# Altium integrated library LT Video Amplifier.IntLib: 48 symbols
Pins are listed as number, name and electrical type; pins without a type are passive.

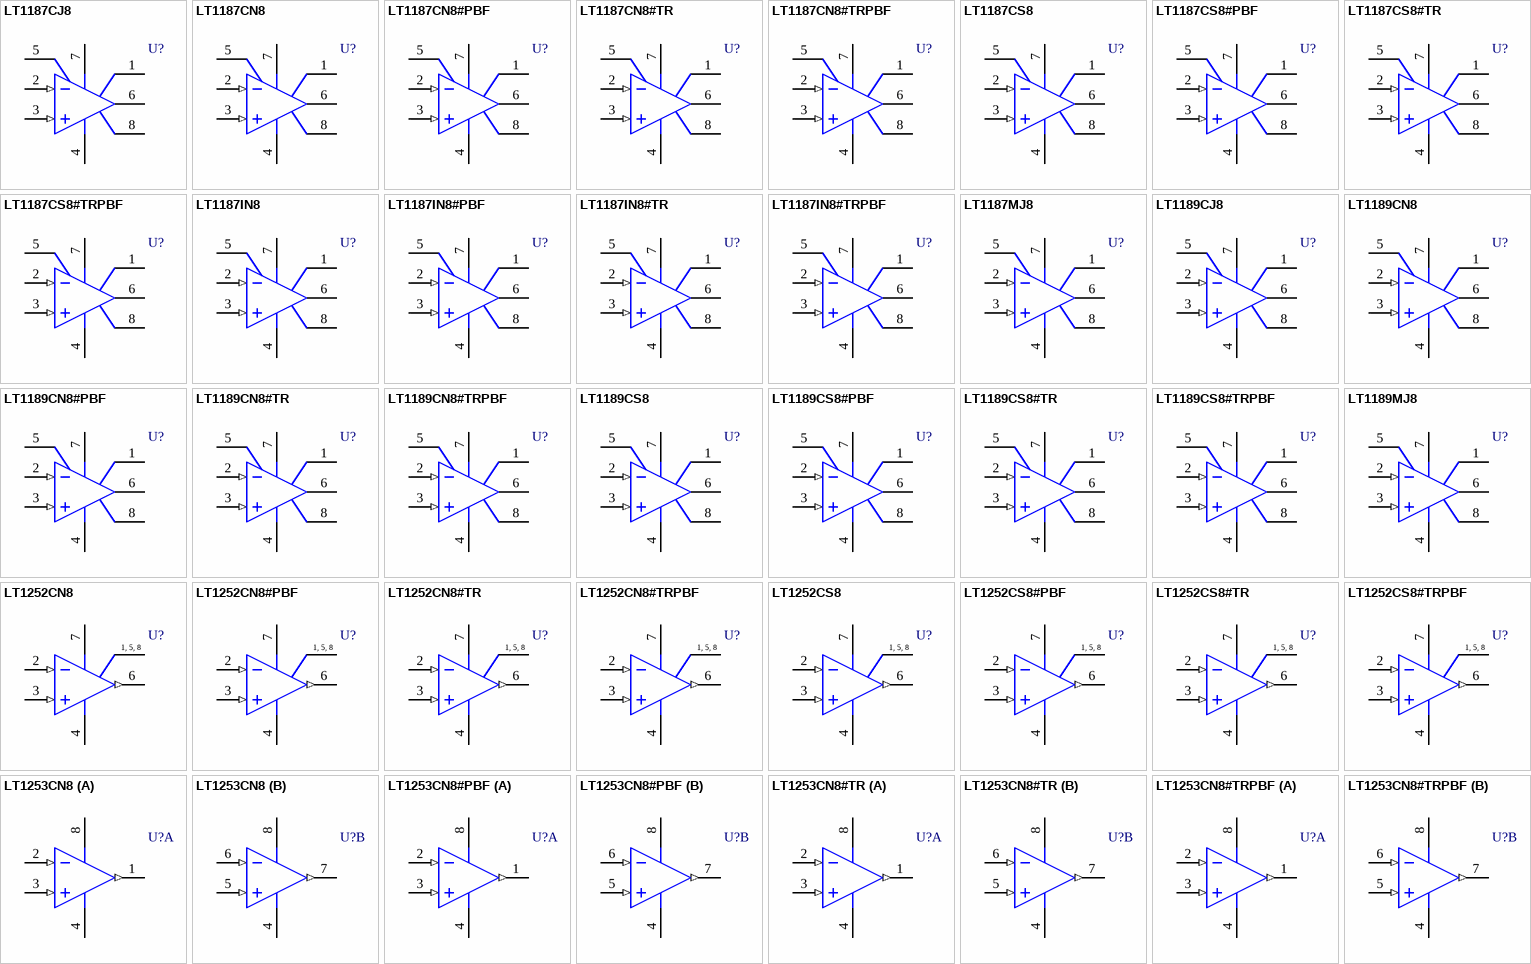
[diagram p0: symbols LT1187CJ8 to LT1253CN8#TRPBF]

## LT1187CJ8
designator U?
Low Power Video Difference Amplifier; Note: 633
footprint J8 (DIP, 8-Leads, Row Spacing 7.62mm, Pitch 2.54mm, Body 9.89x6.73mm)
3D model J8 (DIP, Ceramic, 8-Pin, Row Spacing 7.62 mm, Pitch 2.54 mm)
simulation model LT1187 (SUBCKT)
pins: 1 +/REF, 2 IN- (in), 3 IN+ (in), 4 V- (power), 5 S/D, 6 OUT (hiz), 7 V+ (power), 8 -/FBK

## LT1187CN8
designator U?
Low Power Video Difference Amplifier; Note: 634
footprint N8 (DIP, 8-Leads, Row Spacing 7.62mm, Pitch 2.54mm, Body 9.78x6.48mm)
3D model N8 (DIP, Plastic, 8-Pin, Row Spacing 7.62 mm, Pitch 2.54 mm)
simulation model LT1187 (SUBCKT)
pins: 1 +/REF, 2 IN- (in), 3 IN+ (in), 4 V- (power), 5 S/D, 6 OUT (hiz), 7 V+ (power), 8 -/FBK

## LT1187CN8#PBF
designator U?
Low Power Video Difference Amplifier; Note: 636
footprint N8 (DIP, 8-Leads, Row Spacing 7.62mm, Pitch 2.54mm, Body 9.78x6.48mm)
3D model N8 (DIP, Plastic, 8-Pin, Row Spacing 7.62 mm, Pitch 2.54 mm)
simulation model LT1187 (SUBCKT)
pins: 1 +/REF, 2 IN- (in), 3 IN+ (in), 4 V- (power), 5 S/D, 6 OUT (hiz), 7 V+ (power), 8 -/FBK

## LT1187CN8#TR
designator U?
Low Power Video Difference Amplifier; Note: 635
footprint N8 (DIP, 8-Leads, Row Spacing 7.62mm, Pitch 2.54mm, Body 9.78x6.48mm)
3D model N8 (DIP, Plastic, 8-Pin, Row Spacing 7.62 mm, Pitch 2.54 mm)
simulation model LT1187 (SUBCKT)
pins: 1 +/REF, 2 IN- (in), 3 IN+ (in), 4 V- (power), 5 S/D, 6 OUT (hiz), 7 V+ (power), 8 -/FBK

## LT1187CN8#TRPBF
designator U?
Low Power Video Difference Amplifier; Note: 637
footprint N8 (DIP, 8-Leads, Row Spacing 7.62mm, Pitch 2.54mm, Body 9.78x6.48mm)
3D model N8 (DIP, Plastic, 8-Pin, Row Spacing 7.62 mm, Pitch 2.54 mm)
simulation model LT1187 (SUBCKT)
pins: 1 +/REF, 2 IN- (in), 3 IN+ (in), 4 V- (power), 5 S/D, 6 OUT (hiz), 7 V+ (power), 8 -/FBK

## LT1187CS8
designator U?
Low Power Video Difference Amplifier; Note: 638
footprint S8_N (SOIC, 8-Leads, Body 4.9x3.9mm, Pitch 1.27mm, IPC Medium Density)
footprint S8_L (SOIC, 8-Leads, Body 4.9x3.9mm, Pitch 1.27mm, IPC High Density)
footprint S8_M (SOIC, 8-Leads, Body 4.9x3.9mm, Pitch 1.27mm, IPC Low Density)
3D model S8 (8-Pin Small Outline Integrated Circuit 1.27 mm Pitch)
simulation model LT1187 (SUBCKT)
pins: 1 +/REF, 2 IN- (in), 3 IN+ (in), 4 V- (power), 5 S/D, 6 OUT (hiz), 7 V+ (power), 8 -/FBK

## LT1187CS8#PBF
designator U?
Low Power Video Difference Amplifier; Note: 640
footprint S8_N (SOIC, 8-Leads, Body 4.9x3.9mm, Pitch 1.27mm, IPC Medium Density)
footprint S8_L (SOIC, 8-Leads, Body 4.9x3.9mm, Pitch 1.27mm, IPC High Density)
footprint S8_M (SOIC, 8-Leads, Body 4.9x3.9mm, Pitch 1.27mm, IPC Low Density)
3D model S8 (8-Pin Small Outline Integrated Circuit 1.27 mm Pitch)
simulation model LT1187 (SUBCKT)
pins: 1 +/REF, 2 IN- (in), 3 IN+ (in), 4 V- (power), 5 S/D, 6 OUT (hiz), 7 V+ (power), 8 -/FBK

## LT1187CS8#TR
designator U?
Low Power Video Difference Amplifier; Note: 639
footprint S8_N (SOIC, 8-Leads, Body 4.9x3.9mm, Pitch 1.27mm, IPC Medium Density)
footprint S8_L (SOIC, 8-Leads, Body 4.9x3.9mm, Pitch 1.27mm, IPC High Density)
footprint S8_M (SOIC, 8-Leads, Body 4.9x3.9mm, Pitch 1.27mm, IPC Low Density)
3D model S8 (8-Pin Small Outline Integrated Circuit 1.27 mm Pitch)
simulation model LT1187 (SUBCKT)
pins: 1 +/REF, 2 IN- (in), 3 IN+ (in), 4 V- (power), 5 S/D, 6 OUT (hiz), 7 V+ (power), 8 -/FBK

## LT1187CS8#TRPBF
designator U?
Low Power Video Difference Amplifier; Note: 641
footprint S8_N (SOIC, 8-Leads, Body 4.9x3.9mm, Pitch 1.27mm, IPC Medium Density)
footprint S8_L (SOIC, 8-Leads, Body 4.9x3.9mm, Pitch 1.27mm, IPC High Density)
footprint S8_M (SOIC, 8-Leads, Body 4.9x3.9mm, Pitch 1.27mm, IPC Low Density)
3D model S8 (8-Pin Small Outline Integrated Circuit 1.27 mm Pitch)
simulation model LT1187 (SUBCKT)
pins: 1 +/REF, 2 IN- (in), 3 IN+ (in), 4 V- (power), 5 S/D, 6 OUT (hiz), 7 V+ (power), 8 -/FBK

## LT1187IN8
designator U?
Low Power Video Difference Amplifier; Note: 642
footprint N8 (DIP, 8-Leads, Row Spacing 7.62mm, Pitch 2.54mm, Body 9.78x6.48mm)
3D model N8 (DIP, Plastic, 8-Pin, Row Spacing 7.62 mm, Pitch 2.54 mm)
simulation model LT1187 (SUBCKT)
pins: 1 +/REF, 2 IN- (in), 3 IN+ (in), 4 V- (power), 5 S/D, 6 OUT (hiz), 7 V+ (power), 8 -/FBK

## LT1187IN8#PBF
designator U?
Low Power Video Difference Amplifier; Note: 644
footprint N8 (DIP, 8-Leads, Row Spacing 7.62mm, Pitch 2.54mm, Body 9.78x6.48mm)
3D model N8 (DIP, Plastic, 8-Pin, Row Spacing 7.62 mm, Pitch 2.54 mm)
simulation model LT1187 (SUBCKT)
pins: 1 +/REF, 2 IN- (in), 3 IN+ (in), 4 V- (power), 5 S/D, 6 OUT (hiz), 7 V+ (power), 8 -/FBK

## LT1187IN8#TR
designator U?
Low Power Video Difference Amplifier; Note: 643
footprint N8 (DIP, 8-Leads, Row Spacing 7.62mm, Pitch 2.54mm, Body 9.78x6.48mm)
3D model N8 (DIP, Plastic, 8-Pin, Row Spacing 7.62 mm, Pitch 2.54 mm)
simulation model LT1187 (SUBCKT)
pins: 1 +/REF, 2 IN- (in), 3 IN+ (in), 4 V- (power), 5 S/D, 6 OUT (hiz), 7 V+ (power), 8 -/FBK

## LT1187IN8#TRPBF
designator U?
Low Power Video Difference Amplifier; Note: 645
footprint N8 (DIP, 8-Leads, Row Spacing 7.62mm, Pitch 2.54mm, Body 9.78x6.48mm)
3D model N8 (DIP, Plastic, 8-Pin, Row Spacing 7.62 mm, Pitch 2.54 mm)
simulation model LT1187 (SUBCKT)
pins: 1 +/REF, 2 IN- (in), 3 IN+ (in), 4 V- (power), 5 S/D, 6 OUT (hiz), 7 V+ (power), 8 -/FBK

## LT1187MJ8
designator U?
Low Power Video Difference Amplifier; Note: 646
footprint J8 (DIP, 8-Leads, Row Spacing 7.62mm, Pitch 2.54mm, Body 9.89x6.73mm)
3D model J8 (DIP, Ceramic, 8-Pin, Row Spacing 7.62 mm, Pitch 2.54 mm)
simulation model LT1187 (SUBCKT)
pins: 1 +/REF, 2 IN- (in), 3 IN+ (in), 4 V- (power), 5 S/D, 6 OUT (hiz), 7 V+ (power), 8 -/FBK

## LT1189CJ8
designator U?
Low Power Video Difference Amplifier; Note: 647
footprint J8 (DIP, 8-Leads, Row Spacing 7.62mm, Pitch 2.54mm, Body 9.89x6.73mm)
3D model J8 (DIP, Ceramic, 8-Pin, Row Spacing 7.62 mm, Pitch 2.54 mm)
simulation model LT1189 (SUBCKT)
pins: 1 +/REF, 2 IN- (in), 3 IN+ (in), 4 V- (power), 5 S/D, 6 OUT (hiz), 7 V+ (power), 8 -/FBK

## LT1189CN8
designator U?
Low Power Video Difference Amplifier; Note: 648
footprint N8 (DIP, 8-Leads, Row Spacing 7.62mm, Pitch 2.54mm, Body 9.78x6.48mm)
3D model N8 (DIP, Plastic, 8-Pin, Row Spacing 7.62 mm, Pitch 2.54 mm)
simulation model LT1189 (SUBCKT)
pins: 1 +/REF, 2 IN- (in), 3 IN+ (in), 4 V- (power), 5 S/D, 6 OUT (hiz), 7 V+ (power), 8 -/FBK

## LT1189CN8#PBF
designator U?
Low Power Video Difference Amplifier; Note: 650
footprint N8 (DIP, 8-Leads, Row Spacing 7.62mm, Pitch 2.54mm, Body 9.78x6.48mm)
3D model N8 (DIP, Plastic, 8-Pin, Row Spacing 7.62 mm, Pitch 2.54 mm)
simulation model LT1189 (SUBCKT)
pins: 1 +/REF, 2 IN- (in), 3 IN+ (in), 4 V- (power), 5 S/D, 6 OUT (hiz), 7 V+ (power), 8 -/FBK

## LT1189CN8#TR
designator U?
Low Power Video Difference Amplifier; Note: 649
footprint N8 (DIP, 8-Leads, Row Spacing 7.62mm, Pitch 2.54mm, Body 9.78x6.48mm)
3D model N8 (DIP, Plastic, 8-Pin, Row Spacing 7.62 mm, Pitch 2.54 mm)
simulation model LT1189 (SUBCKT)
pins: 1 +/REF, 2 IN- (in), 3 IN+ (in), 4 V- (power), 5 S/D, 6 OUT (hiz), 7 V+ (power), 8 -/FBK

## LT1189CN8#TRPBF
designator U?
Low Power Video Difference Amplifier; Note: 651
footprint N8 (DIP, 8-Leads, Row Spacing 7.62mm, Pitch 2.54mm, Body 9.78x6.48mm)
3D model N8 (DIP, Plastic, 8-Pin, Row Spacing 7.62 mm, Pitch 2.54 mm)
simulation model LT1189 (SUBCKT)
pins: 1 +/REF, 2 IN- (in), 3 IN+ (in), 4 V- (power), 5 S/D, 6 OUT (hiz), 7 V+ (power), 8 -/FBK

## LT1189CS8
designator U?
Low Power Video Difference Amplifier; Note: 652
footprint S8_N (SOIC, 8-Leads, Body 4.9x3.9mm, Pitch 1.27mm, IPC Medium Density)
footprint S8_L (SOIC, 8-Leads, Body 4.9x3.9mm, Pitch 1.27mm, IPC High Density)
footprint S8_M (SOIC, 8-Leads, Body 4.9x3.9mm, Pitch 1.27mm, IPC Low Density)
3D model S8 (8-Pin Small Outline Integrated Circuit 1.27 mm Pitch)
simulation model LT1189 (SUBCKT)
pins: 1 +/REF, 2 IN- (in), 3 IN+ (in), 4 V- (power), 5 S/D, 6 OUT (hiz), 7 V+ (power), 8 -/FBK

## LT1189CS8#PBF
designator U?
Low Power Video Difference Amplifier; Note: 654
footprint S8_N (SOIC, 8-Leads, Body 4.9x3.9mm, Pitch 1.27mm, IPC Medium Density)
footprint S8_L (SOIC, 8-Leads, Body 4.9x3.9mm, Pitch 1.27mm, IPC High Density)
footprint S8_M (SOIC, 8-Leads, Body 4.9x3.9mm, Pitch 1.27mm, IPC Low Density)
3D model S8 (8-Pin Small Outline Integrated Circuit 1.27 mm Pitch)
simulation model LT1189 (SUBCKT)
pins: 1 +/REF, 2 IN- (in), 3 IN+ (in), 4 V- (power), 5 S/D, 6 OUT (hiz), 7 V+ (power), 8 -/FBK

## LT1189CS8#TR
designator U?
Low Power Video Difference Amplifier; Note: 653
footprint S8_N (SOIC, 8-Leads, Body 4.9x3.9mm, Pitch 1.27mm, IPC Medium Density)
footprint S8_L (SOIC, 8-Leads, Body 4.9x3.9mm, Pitch 1.27mm, IPC High Density)
footprint S8_M (SOIC, 8-Leads, Body 4.9x3.9mm, Pitch 1.27mm, IPC Low Density)
3D model S8 (8-Pin Small Outline Integrated Circuit 1.27 mm Pitch)
simulation model LT1189 (SUBCKT)
pins: 1 +/REF, 2 IN- (in), 3 IN+ (in), 4 V- (power), 5 S/D, 6 OUT (hiz), 7 V+ (power), 8 -/FBK

## LT1189CS8#TRPBF
designator U?
Low Power Video Difference Amplifier; Note: 655
footprint S8_N (SOIC, 8-Leads, Body 4.9x3.9mm, Pitch 1.27mm, IPC Medium Density)
footprint S8_L (SOIC, 8-Leads, Body 4.9x3.9mm, Pitch 1.27mm, IPC High Density)
footprint S8_M (SOIC, 8-Leads, Body 4.9x3.9mm, Pitch 1.27mm, IPC Low Density)
3D model S8 (8-Pin Small Outline Integrated Circuit 1.27 mm Pitch)
simulation model LT1189 (SUBCKT)
pins: 1 +/REF, 2 IN- (in), 3 IN+ (in), 4 V- (power), 5 S/D, 6 OUT (hiz), 7 V+ (power), 8 -/FBK

## LT1189MJ8
designator U?
Low Power Video Difference Amplifier; Note: 656
footprint J8 (DIP, 8-Leads, Row Spacing 7.62mm, Pitch 2.54mm, Body 9.89x6.73mm)
3D model J8 (DIP, Ceramic, 8-Pin, Row Spacing 7.62 mm, Pitch 2.54 mm)
simulation model LT1189 (SUBCKT)
pins: 1 +/REF, 2 IN- (in), 3 IN+ (in), 4 V- (power), 5 S/D, 6 OUT (hiz), 7 V+ (power), 8 -/FBK

## LT1252CN8
designator U?
Low Cost Video Amplifier; Note: Pins 1, 5 and 8 are NC (not internally connected) pins.; Note: 991
footprint N8 (DIP, 8-Leads, Row Spacing 7.62mm, Pitch 2.54mm, Body 9.78x6.48mm)
3D model N8 (DIP, Plastic, 8-Pin, Row Spacing 7.62 mm, Pitch 2.54 mm)
simulation model LT1252 (SUBCKT)
pins: 1 NC, 2 IN- (in), 3 IN+ (in), 4 V- (power), 5 NC, 6 OUT (out), 7 V+ (power), 8 NC

## LT1252CN8#PBF
designator U?
Low Cost Video Amplifier; Note: Pins 1, 5 and 8 are NC (not internally connected) pins.; Note: 993
footprint N8 (DIP, 8-Leads, Row Spacing 7.62mm, Pitch 2.54mm, Body 9.78x6.48mm)
3D model N8 (DIP, Plastic, 8-Pin, Row Spacing 7.62 mm, Pitch 2.54 mm)
simulation model LT1252 (SUBCKT)
pins: 1 NC, 2 IN- (in), 3 IN+ (in), 4 V- (power), 5 NC, 6 OUT (out), 7 V+ (power), 8 NC

## LT1252CN8#TR
designator U?
Low Cost Video Amplifier; Note: Pins 1, 5 and 8 are NC (not internally connected) pins.; Note: 992
footprint N8 (DIP, 8-Leads, Row Spacing 7.62mm, Pitch 2.54mm, Body 9.78x6.48mm)
3D model N8 (DIP, Plastic, 8-Pin, Row Spacing 7.62 mm, Pitch 2.54 mm)
simulation model LT1252 (SUBCKT)
pins: 1 NC, 2 IN- (in), 3 IN+ (in), 4 V- (power), 5 NC, 6 OUT (out), 7 V+ (power), 8 NC

## LT1252CN8#TRPBF
designator U?
Low Cost Video Amplifier; Note: Pins 1, 5 and 8 are NC (not internally connected) pins.; Note: 994
footprint N8 (DIP, 8-Leads, Row Spacing 7.62mm, Pitch 2.54mm, Body 9.78x6.48mm)
3D model N8 (DIP, Plastic, 8-Pin, Row Spacing 7.62 mm, Pitch 2.54 mm)
simulation model LT1252 (SUBCKT)
pins: 1 NC, 2 IN- (in), 3 IN+ (in), 4 V- (power), 5 NC, 6 OUT (out), 7 V+ (power), 8 NC

## LT1252CS8
designator U?
Low Cost Video Amplifier; Note: Pins 1, 5 and 8 are NC (not internally connected) pins.; Note: 995
footprint S8_N (SOIC, 8-Leads, Body 4.9x3.9mm, Pitch 1.27mm, IPC Medium Density)
footprint S8_L (SOIC, 8-Leads, Body 4.9x3.9mm, Pitch 1.27mm, IPC High Density)
footprint S8_M (SOIC, 8-Leads, Body 4.9x3.9mm, Pitch 1.27mm, IPC Low Density)
3D model S8 (8-Pin Small Outline Integrated Circuit 1.27 mm Pitch)
simulation model LT1252 (SUBCKT)
pins: 1 NC, 2 IN- (in), 3 IN+ (in), 4 V- (power), 5 NC, 6 OUT (out), 7 V+ (power), 8 NC

## LT1252CS8#PBF
designator U?
Low Cost Video Amplifier; Note: Pins 1, 5 and 8 are NC (not internally connected) pins.; Note: 997
footprint S8_N (SOIC, 8-Leads, Body 4.9x3.9mm, Pitch 1.27mm, IPC Medium Density)
footprint S8_L (SOIC, 8-Leads, Body 4.9x3.9mm, Pitch 1.27mm, IPC High Density)
footprint S8_M (SOIC, 8-Leads, Body 4.9x3.9mm, Pitch 1.27mm, IPC Low Density)
3D model S8 (8-Pin Small Outline Integrated Circuit 1.27 mm Pitch)
simulation model LT1252 (SUBCKT)
pins: 1 NC, 2 IN- (in), 3 IN+ (in), 4 V- (power), 5 NC, 6 OUT (out), 7 V+ (power), 8 NC

## LT1252CS8#TR
designator U?
Low Cost Video Amplifier; Note: Pins 1, 5 and 8 are NC (not internally connected) pins.; Note: 996
footprint S8_N (SOIC, 8-Leads, Body 4.9x3.9mm, Pitch 1.27mm, IPC Medium Density)
footprint S8_L (SOIC, 8-Leads, Body 4.9x3.9mm, Pitch 1.27mm, IPC High Density)
footprint S8_M (SOIC, 8-Leads, Body 4.9x3.9mm, Pitch 1.27mm, IPC Low Density)
3D model S8 (8-Pin Small Outline Integrated Circuit 1.27 mm Pitch)
simulation model LT1252 (SUBCKT)
pins: 1 NC, 2 IN- (in), 3 IN+ (in), 4 V- (power), 5 NC, 6 OUT (out), 7 V+ (power), 8 NC

## LT1252CS8#TRPBF
designator U?
Low Cost Video Amplifier; Note: Pins 1, 5 and 8 are NC (not internally connected) pins.; Note: 998
footprint S8_N (SOIC, 8-Leads, Body 4.9x3.9mm, Pitch 1.27mm, IPC Medium Density)
footprint S8_L (SOIC, 8-Leads, Body 4.9x3.9mm, Pitch 1.27mm, IPC High Density)
footprint S8_M (SOIC, 8-Leads, Body 4.9x3.9mm, Pitch 1.27mm, IPC Low Density)
3D model S8 (8-Pin Small Outline Integrated Circuit 1.27 mm Pitch)
simulation model LT1252 (SUBCKT)
pins: 1 NC, 2 IN- (in), 3 IN+ (in), 4 V- (power), 5 NC, 6 OUT (out), 7 V+ (power), 8 NC

## LT1253CN8
designator U?
Low Cost Dual Video Amplifier; Note: 999
footprint N8 (DIP, 8-Leads, Row Spacing 7.62mm, Pitch 2.54mm, Body 9.78x6.48mm)
3D model N8 (DIP, Plastic, 8-Pin, Row Spacing 7.62 mm, Pitch 2.54 mm)
simulation model LT1253 (SUBCKT)
pins on every part: 4 V- (power), 8 V+ (power)
part A pins: 1 OUT (out), 2 IN- (in), 3 IN+ (in)
part B pins: 5 IN+ (in), 6 IN- (in), 7 OUT (out)

## LT1253CN8#PBF
designator U?
Low Cost Dual Video Amplifier; Note: 1001
footprint N8 (DIP, 8-Leads, Row Spacing 7.62mm, Pitch 2.54mm, Body 9.78x6.48mm)
3D model N8 (DIP, Plastic, 8-Pin, Row Spacing 7.62 mm, Pitch 2.54 mm)
simulation model LT1253 (SUBCKT)
pins on every part: 4 V- (power), 8 V+ (power)
part A pins: 1 OUT (out), 2 IN- (in), 3 IN+ (in)
part B pins: 5 IN+ (in), 6 IN- (in), 7 OUT (out)

## LT1253CN8#TR
designator U?
Low Cost Dual Video Amplifier; Note: 1000
footprint N8 (DIP, 8-Leads, Row Spacing 7.62mm, Pitch 2.54mm, Body 9.78x6.48mm)
3D model N8 (DIP, Plastic, 8-Pin, Row Spacing 7.62 mm, Pitch 2.54 mm)
simulation model LT1253 (SUBCKT)
pins on every part: 4 V- (power), 8 V+ (power)
part A pins: 1 OUT (out), 2 IN- (in), 3 IN+ (in)
part B pins: 5 IN+ (in), 6 IN- (in), 7 OUT (out)

## LT1253CN8#TRPBF
designator U?
Low Cost Dual Video Amplifier; Note: 1002
footprint N8 (DIP, 8-Leads, Row Spacing 7.62mm, Pitch 2.54mm, Body 9.78x6.48mm)
3D model N8 (DIP, Plastic, 8-Pin, Row Spacing 7.62 mm, Pitch 2.54 mm)
simulation model LT1253 (SUBCKT)
pins on every part: 4 V- (power), 8 V+ (power)
part A pins: 1 OUT (out), 2 IN- (in), 3 IN+ (in)
part B pins: 5 IN+ (in), 6 IN- (in), 7 OUT (out)

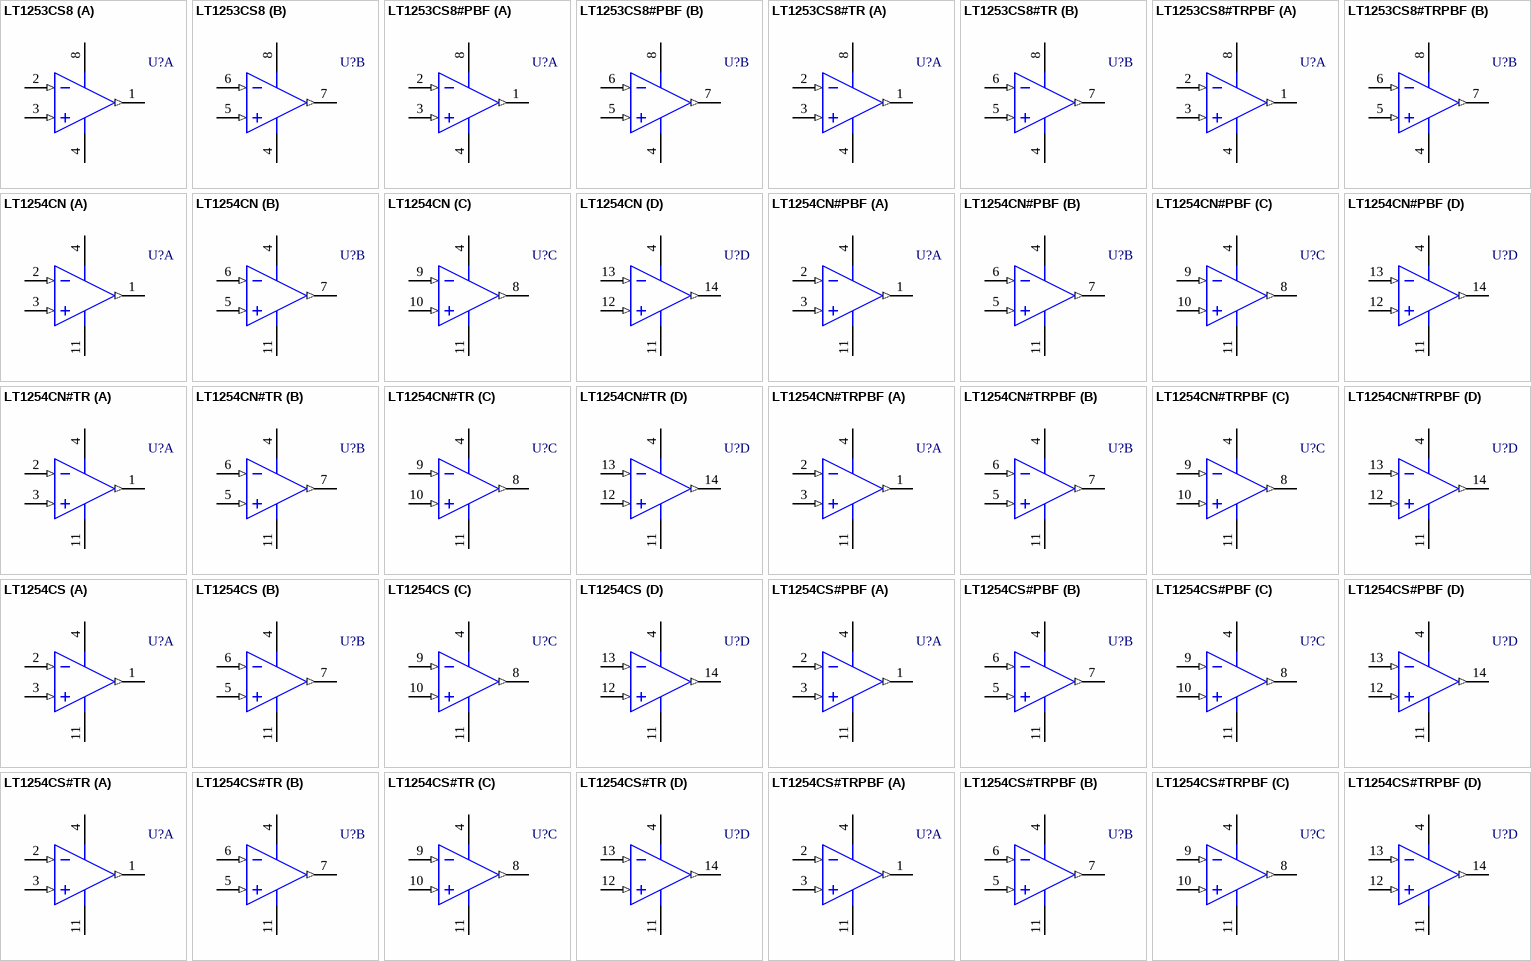
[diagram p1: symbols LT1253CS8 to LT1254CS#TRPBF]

## LT1253CS8
designator U?
Low Cost Dual Video Amplifier; Note: 1003
footprint S8_N (SOIC, 8-Leads, Body 4.9x3.9mm, Pitch 1.27mm, IPC Medium Density)
footprint S8_L (SOIC, 8-Leads, Body 4.9x3.9mm, Pitch 1.27mm, IPC High Density)
footprint S8_M (SOIC, 8-Leads, Body 4.9x3.9mm, Pitch 1.27mm, IPC Low Density)
3D model S8 (8-Pin Small Outline Integrated Circuit 1.27 mm Pitch)
simulation model LT1253 (SUBCKT)
pins on every part: 4 V- (power), 8 V+ (power)
part A pins: 1 OUT (out), 2 IN- (in), 3 IN+ (in)
part B pins: 5 IN+ (in), 6 IN- (in), 7 OUT (out)

## LT1253CS8#PBF
designator U?
Low Cost Dual Video Amplifier; Note: 1005
footprint S8_N (SOIC, 8-Leads, Body 4.9x3.9mm, Pitch 1.27mm, IPC Medium Density)
footprint S8_L (SOIC, 8-Leads, Body 4.9x3.9mm, Pitch 1.27mm, IPC High Density)
footprint S8_M (SOIC, 8-Leads, Body 4.9x3.9mm, Pitch 1.27mm, IPC Low Density)
3D model S8 (8-Pin Small Outline Integrated Circuit 1.27 mm Pitch)
simulation model LT1253 (SUBCKT)
pins on every part: 4 V- (power), 8 V+ (power)
part A pins: 1 OUT (out), 2 IN- (in), 3 IN+ (in)
part B pins: 5 IN+ (in), 6 IN- (in), 7 OUT (out)

## LT1253CS8#TR
designator U?
Low Cost Dual Video Amplifier; Note: 1004
footprint S8_N (SOIC, 8-Leads, Body 4.9x3.9mm, Pitch 1.27mm, IPC Medium Density)
footprint S8_L (SOIC, 8-Leads, Body 4.9x3.9mm, Pitch 1.27mm, IPC High Density)
footprint S8_M (SOIC, 8-Leads, Body 4.9x3.9mm, Pitch 1.27mm, IPC Low Density)
3D model S8 (8-Pin Small Outline Integrated Circuit 1.27 mm Pitch)
simulation model LT1253 (SUBCKT)
pins on every part: 4 V- (power), 8 V+ (power)
part A pins: 1 OUT (out), 2 IN- (in), 3 IN+ (in)
part B pins: 5 IN+ (in), 6 IN- (in), 7 OUT (out)

## LT1253CS8#TRPBF
designator U?
Low Cost Dual Video Amplifier; Note: 1006
footprint S8_N (SOIC, 8-Leads, Body 4.9x3.9mm, Pitch 1.27mm, IPC Medium Density)
footprint S8_L (SOIC, 8-Leads, Body 4.9x3.9mm, Pitch 1.27mm, IPC High Density)
footprint S8_M (SOIC, 8-Leads, Body 4.9x3.9mm, Pitch 1.27mm, IPC Low Density)
3D model S8 (8-Pin Small Outline Integrated Circuit 1.27 mm Pitch)
simulation model LT1253 (SUBCKT)
pins on every part: 4 V- (power), 8 V+ (power)
part A pins: 1 OUT (out), 2 IN- (in), 3 IN+ (in)
part B pins: 5 IN+ (in), 6 IN- (in), 7 OUT (out)

## LT1254CN
designator U?
Low Cost Quad Video Amplifier; Note: 1007
footprint N14 (DIP, 14-Leads, Row Spacing 7.62mm, Pitch 2.54mm, Body 19.18x6.48mm)
3D model N14 (DIP, Plastic, 14-Pin, Row Spacing 7.62 mm, Pitch 2.54 mm)
simulation model LT1254 (SUBCKT)
pins on every part: 4 V+ (power), 11 V- (power)
part A pins: 1 OUT (out), 2 IN- (in), 3 IN+ (in)
part B pins: 5 IN+ (in), 6 IN- (in), 7 OUT (out)
part C pins: 8 OUT (out), 9 IN- (in), 10 IN+ (in)
part D pins: 12 IN+ (in), 13 IN- (in), 14 OUT (out)

## LT1254CN#PBF
designator U?
Low Cost Quad Video Amplifier; Note: 1009
footprint N14 (DIP, 14-Leads, Row Spacing 7.62mm, Pitch 2.54mm, Body 19.18x6.48mm)
3D model N14 (DIP, Plastic, 14-Pin, Row Spacing 7.62 mm, Pitch 2.54 mm)
simulation model LT1254 (SUBCKT)
pins on every part: 4 V+ (power), 11 V- (power)
part A pins: 1 OUT (out), 2 IN- (in), 3 IN+ (in)
part B pins: 5 IN+ (in), 6 IN- (in), 7 OUT (out)
part C pins: 8 OUT (out), 9 IN- (in), 10 IN+ (in)
part D pins: 12 IN+ (in), 13 IN- (in), 14 OUT (out)

## LT1254CN#TR
designator U?
Low Cost Quad Video Amplifier; Note: 1008
footprint N14 (DIP, 14-Leads, Row Spacing 7.62mm, Pitch 2.54mm, Body 19.18x6.48mm)
3D model N14 (DIP, Plastic, 14-Pin, Row Spacing 7.62 mm, Pitch 2.54 mm)
simulation model LT1254 (SUBCKT)
pins on every part: 4 V+ (power), 11 V- (power)
part A pins: 1 OUT (out), 2 IN- (in), 3 IN+ (in)
part B pins: 5 IN+ (in), 6 IN- (in), 7 OUT (out)
part C pins: 8 OUT (out), 9 IN- (in), 10 IN+ (in)
part D pins: 12 IN+ (in), 13 IN- (in), 14 OUT (out)

## LT1254CN#TRPBF
designator U?
Low Cost Quad Video Amplifier; Note: 1010
footprint N14 (DIP, 14-Leads, Row Spacing 7.62mm, Pitch 2.54mm, Body 19.18x6.48mm)
3D model N14 (DIP, Plastic, 14-Pin, Row Spacing 7.62 mm, Pitch 2.54 mm)
simulation model LT1254 (SUBCKT)
pins on every part: 4 V+ (power), 11 V- (power)
part A pins: 1 OUT (out), 2 IN- (in), 3 IN+ (in)
part B pins: 5 IN+ (in), 6 IN- (in), 7 OUT (out)
part C pins: 8 OUT (out), 9 IN- (in), 10 IN+ (in)
part D pins: 12 IN+ (in), 13 IN- (in), 14 OUT (out)

## LT1254CS
designator U?
Low Cost Quad Video Amplifier; Note: 1011
footprint S14_N (SOIC, 14-Leads, Body 8.6x3.9mm, Pitch 1.27mm, IPC Medium Density)
footprint S14_L (SOIC, 14-Leads, Body 8.6x3.9mm, Pitch 1.27mm, IPC High Density)
footprint S14_M (SOIC, 14-Leads, Body 8.6x3.9mm, Pitch 1.27mm, IPC Low Density)
3D model S14 (14-Pin Small Outline Integrated Circuit 1.27 mm Pitch)
simulation model LT1254 (SUBCKT)
pins on every part: 4 V+ (power), 11 V- (power)
part A pins: 1 OUT (out), 2 IN- (in), 3 IN+ (in)
part B pins: 5 IN+ (in), 6 IN- (in), 7 OUT (out)
part C pins: 8 OUT (out), 9 IN- (in), 10 IN+ (in)
part D pins: 12 IN+ (in), 13 IN- (in), 14 OUT (out)

## LT1254CS#PBF
designator U?
Low Cost Quad Video Amplifier; Note: 1013
footprint S14_N (SOIC, 14-Leads, Body 8.6x3.9mm, Pitch 1.27mm, IPC Medium Density)
footprint S14_L (SOIC, 14-Leads, Body 8.6x3.9mm, Pitch 1.27mm, IPC High Density)
footprint S14_M (SOIC, 14-Leads, Body 8.6x3.9mm, Pitch 1.27mm, IPC Low Density)
3D model S14 (14-Pin Small Outline Integrated Circuit 1.27 mm Pitch)
simulation model LT1254 (SUBCKT)
pins on every part: 4 V+ (power), 11 V- (power)
part A pins: 1 OUT (out), 2 IN- (in), 3 IN+ (in)
part B pins: 5 IN+ (in), 6 IN- (in), 7 OUT (out)
part C pins: 8 OUT (out), 9 IN- (in), 10 IN+ (in)
part D pins: 12 IN+ (in), 13 IN- (in), 14 OUT (out)

## LT1254CS#TR
designator U?
Low Cost Quad Video Amplifier; Note: 1012
footprint S14_N (SOIC, 14-Leads, Body 8.6x3.9mm, Pitch 1.27mm, IPC Medium Density)
footprint S14_L (SOIC, 14-Leads, Body 8.6x3.9mm, Pitch 1.27mm, IPC High Density)
footprint S14_M (SOIC, 14-Leads, Body 8.6x3.9mm, Pitch 1.27mm, IPC Low Density)
3D model S14 (14-Pin Small Outline Integrated Circuit 1.27 mm Pitch)
simulation model LT1254 (SUBCKT)
pins on every part: 4 V+ (power), 11 V- (power)
part A pins: 1 OUT (out), 2 IN- (in), 3 IN+ (in)
part B pins: 5 IN+ (in), 6 IN- (in), 7 OUT (out)
part C pins: 8 OUT (out), 9 IN- (in), 10 IN+ (in)
part D pins: 12 IN+ (in), 13 IN- (in), 14 OUT (out)

## LT1254CS#TRPBF
designator U?
Low Cost Quad Video Amplifier; Note: 1014
footprint S14_N (SOIC, 14-Leads, Body 8.6x3.9mm, Pitch 1.27mm, IPC Medium Density)
footprint S14_L (SOIC, 14-Leads, Body 8.6x3.9mm, Pitch 1.27mm, IPC High Density)
footprint S14_M (SOIC, 14-Leads, Body 8.6x3.9mm, Pitch 1.27mm, IPC Low Density)
3D model S14 (14-Pin Small Outline Integrated Circuit 1.27 mm Pitch)
simulation model LT1254 (SUBCKT)
pins on every part: 4 V+ (power), 11 V- (power)
part A pins: 1 OUT (out), 2 IN- (in), 3 IN+ (in)
part B pins: 5 IN+ (in), 6 IN- (in), 7 OUT (out)
part C pins: 8 OUT (out), 9 IN- (in), 10 IN+ (in)
part D pins: 12 IN+ (in), 13 IN- (in), 14 OUT (out)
